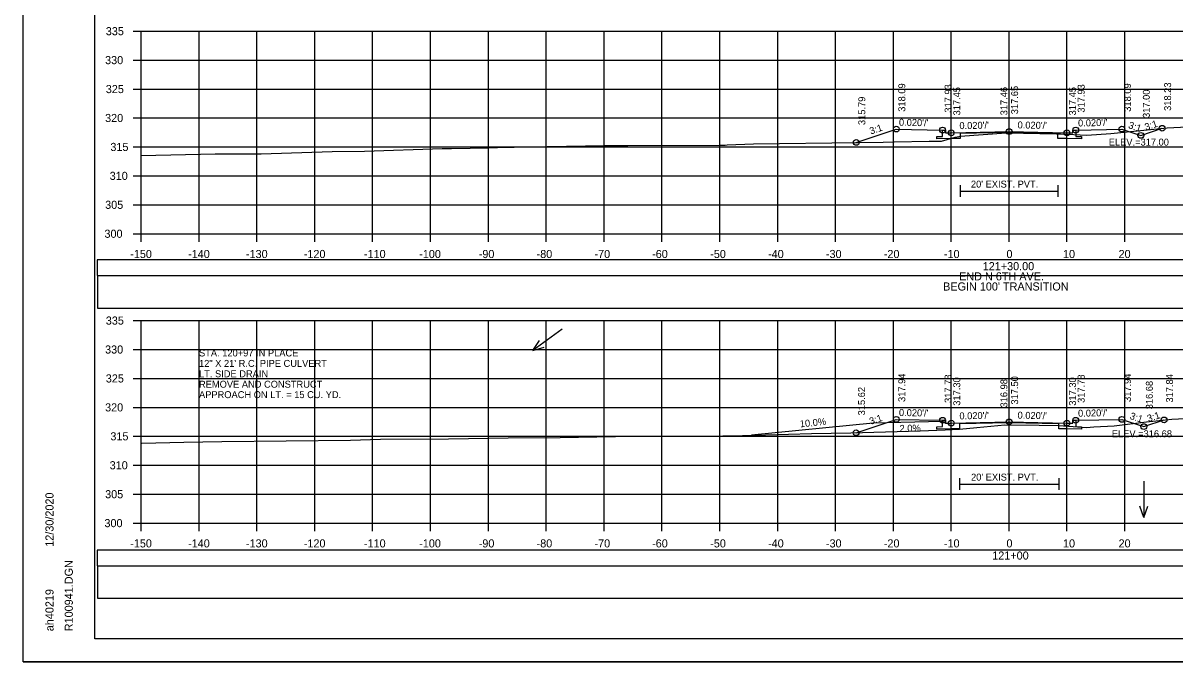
# Model space of a CAD drawing. Extents: x 1370538 to 1372872, y 376220 to 381127.
# Drawn here: x 1371871.6 to 1372070.6, y 380471.7 to 380582.1 of the extents above; entities that cross this region are included whole.
import ezdxf

# ---------------------------------------------------------------- set-up
doc = ezdxf.new("R2010")
doc.units = 0
for name, color, linetype in [('R_Border', 7, 'Continuous'), ('R_Border Notes', 7, 'Continuous'), ('R_Border PE', 7, 'Continuous'), ('R_Border Prem', 7, 'Continuous'), ('R_Dimension', 7, 'Continuous'), ('R_Fin Surface', 7, 'Continuous'), ('R_Grid', 7, 'Continuous'), ('R_No Plot', 7, 'Continuous'), ('R_Water', 7, 'Continuous'), ('R_Water Annot', 7, 'Continuous'), ('R_Xsect Elev', 7, 'Continuous'), ('R_Xsect Slope', 7, 'Continuous'), ('T_Detection Zones', 7, 'Continuous')]:
    doc.layers.add(name, color=color, linetype=linetype)

msp = doc.modelspace()

# ---------------------------------------------------------------- linework, layer by layer
at = {"layer": 'R_Border'}
for p, q in [((1372033.53, 380554.09), (1372033.53, 380552.09)), ((1372050.41, 380554.09), (1372050.41, 380552.09)), ((1372033.53, 380553.09), (1372050.41, 380553.09)), ((1372033.41, 380503.46), (1372033.41, 380501.46)), ((1372033.41, 380502.46), (1372050.55, 380502.46)), ((1372050.55, 380503.46), (1372050.55, 380501.46))]:
    msp.add_line(p, q, dxfattribs=at)
for points in [[(1372041.97, 380563.18), (1372033.53, 380563.01), (1372033.53, 380562.18), (1372031.97, 380562.15), (1372029.47, 380562.1), (1372029.47, 380562.52), (1372030.47, 380562.54), (1372030.47, 380563.63)], [(1372053.47, 380563.63), (1372053.47, 380562.54), (1372054.47, 380562.52), (1372054.47, 380562.1), (1372051.97, 380562.15), (1372050.41, 380562.18), (1372050.41, 380563.01), (1372041.97, 380563.18)], [(1372041.97, 380513.03), (1372033.41, 380512.86), (1372033.41, 380512.03), (1372031.97, 380512), (1372029.47, 380511.95), (1372029.47, 380512.37), (1372030.47, 380512.39), (1372030.47, 380513.48)], [(1372053.47, 380513.48), (1372053.47, 380512.39), (1372054.47, 380512.37), (1372054.47, 380511.95), (1372051.97, 380512), (1372050.55, 380512.03), (1372050.55, 380512.86), (1372041.97, 380513.03)]]:
    msp.add_lwpolyline(points, dxfattribs=at)
at = {"layer": 'R_Border Notes'}
for p, q in [((1371883.97, 380475.71), (1371883.97, 380681.17)), ((1371883.97, 380475.71), (1371883.97, 380475.71)), ((1372200.15, 380475.71), (1371883.97, 380475.71))]:
    msp.add_line(p, q, dxfattribs=at)
at = {"layer": 'R_Border Prem'}
for p, q in [((1371890.57, 380580.71), (1371891.97, 380580.71)), ((1371891.97, 380545.71), (1371891.97, 380580.71)), ((1371890.57, 380575.71), (1371891.97, 380575.71)), ((1371890.57, 380570.71), (1371891.97, 380570.71)), ((1371890.57, 380565.71), (1371891.97, 380565.71)), ((1371890.57, 380560.71), (1371891.97, 380560.71)), ((1371890.57, 380555.71), (1371891.97, 380555.71)), ((1371890.57, 380550.71), (1371891.97, 380550.71)), ((1371890.57, 380545.71), (1371891.97, 380545.71)), ((1371891.97, 380545.71), (1372191.97, 380545.71)), ((1371891.97, 380544.31), (1371891.97, 380545.71)), ((1371901.97, 380544.31), (1371901.97, 380545.71)), ((1371911.97, 380544.31), (1371911.97, 380545.71)), ((1371921.97, 380544.31), (1371921.97, 380545.71)), ((1371931.97, 380544.31), (1371931.97, 380545.71)), ((1371941.97, 380544.31), (1371941.97, 380545.71)), ((1371951.97, 380544.31), (1371951.97, 380545.71)), ((1371961.97, 380544.31), (1371961.97, 380545.71)), ((1371971.97, 380544.31), (1371971.97, 380545.71)), ((1371981.97, 380544.31), (1371981.97, 380545.71)), ((1371991.97, 380544.31), (1371991.97, 380545.71)), ((1372001.97, 380544.31), (1372001.97, 380545.71)), ((1372011.97, 380544.31), (1372011.97, 380545.71)), ((1372021.97, 380544.31), (1372021.97, 380545.71)), ((1372031.97, 380544.31), (1372031.97, 380545.71)), ((1372041.97, 380544.31), (1372041.97, 380545.71)), ((1372051.97, 380544.31), (1372051.97, 380545.71)), ((1372061.97, 380544.31), (1372061.97, 380545.71)), ((1371890.57, 380530.71), (1371891.97, 380530.71)), ((1371891.97, 380495.71), (1371891.97, 380530.71)), ((1371890.57, 380525.71), (1371891.97, 380525.71)), ((1371890.57, 380520.71), (1371891.97, 380520.71)), ((1371890.57, 380515.71), (1371891.97, 380515.71)), ((1371890.57, 380510.71), (1371891.97, 380510.71)), ((1371890.57, 380505.71), (1371891.97, 380505.71)), ((1371890.57, 380500.71), (1371891.97, 380500.71)), ((1371890.57, 380495.71), (1371891.97, 380495.71)), ((1371891.97, 380495.71), (1372191.97, 380495.71)), ((1371891.97, 380494.31), (1371891.97, 380495.71)), ((1371901.97, 380494.31), (1371901.97, 380495.71)), ((1371911.97, 380494.31), (1371911.97, 380495.71)), ((1371921.97, 380494.31), (1371921.97, 380495.71)), ((1371931.97, 380494.31), (1371931.97, 380495.71)), ((1371941.97, 380494.31), (1371941.97, 380495.71)), ((1371951.97, 380494.31), (1371951.97, 380495.71)), ((1371961.97, 380494.31), (1371961.97, 380495.71)), ((1371971.97, 380494.31), (1371971.97, 380495.71)), ((1371981.97, 380494.31), (1371981.97, 380495.71)), ((1371991.97, 380494.31), (1371991.97, 380495.71)), ((1372001.97, 380494.31), (1372001.97, 380495.71)), ((1372011.97, 380494.31), (1372011.97, 380495.71)), ((1372021.97, 380494.31), (1372021.97, 380495.71)), ((1372031.97, 380494.31), (1372031.97, 380495.71)), ((1372041.97, 380494.31), (1372041.97, 380495.71)), ((1372051.97, 380494.31), (1372051.97, 380495.71)), ((1372061.97, 380494.31), (1372061.97, 380495.71))]:
    msp.add_line(p, q, dxfattribs=at)
at = {"layer": 'R_Dimension'}
for points in [[(1371891.97, 380559.21), (1371904.78, 380559.49), (1371908.06, 380559.53), (1371912.7, 380559.5), (1371924.98, 380559.91), (1371930.55, 380559.97), (1371943.99, 380560.44), (1371945.59, 380560.45), (1371952.08, 380560.55), (1371953.55, 380560.59), (1371962.11, 380560.76), (1371972.09, 380560.96), (1371976.05, 380560.97), (1371991.87, 380561.03), (1371992.91, 380561.04), (1371993.23, 380561.06), (1371997.8, 380561.25), (1372015.83, 380561.5), (1372020.2, 380561.56), (1372022.08, 380561.57), (1372028.16, 380561.73), (1372029.8, 380561.7), (1372030.27, 380561.69), (1372031.24, 380561.98), (1372032.67, 380562.42), (1372033.3, 380562.54), (1372033.53, 380562.58), (1372041.46, 380563.17), (1372041.59, 380563.17), (1372050.15, 380563), (1372050.41, 380562.99), (1372050.85, 380562.98), (1372055.39, 380562.76), (1372059.54, 380563.05), (1372060.72, 380563.13), (1372062.95, 380563.4), (1372069.26, 380564.02), (1372086.66, 380564.89)], [(1371891.97, 380509.52), (1371892.1, 380509.52), (1371899.34, 380509.72), (1371905.92, 380509.79), (1371928.15, 380510.03), (1371933.31, 380510.21), (1371945.11, 380510.28), (1371955.42, 380510.45), (1371964.39, 380510.51), (1371977.09, 380510.76), (1371986.43, 380510.75), (1371989.02, 380510.76), (1371995.9, 380510.86), (1372007.82, 380511.2), (1372014.63, 380511.3), (1372026.59, 380511.64), (1372030.92, 380511.84), (1372033.41, 380511.97), (1372036.41, 380512.26), (1372041.21, 380512.7), (1372047.16, 380512.61), (1372050.55, 380512.55), (1372053.01, 380512.39), (1372055.36, 380512.25), (1372056.59, 380512.34), (1372060.11, 380512.53), (1372065.7, 380513.19), (1372070.08, 380513.7), (1372082.49, 380514.33)]]:
    msp.add_lwpolyline(points, dxfattribs=at)
at = {"layer": 'R_Fin Surface'}
for points in [[(1372015.56, 380561.49), (1372022.47, 380563.79), (1372030.47, 380563.63), (1372030.97, 380563.63), (1372030.97, 380563.13), (1372031.97, 380563.15), (1372041.97, 380563.35)], [(1372041.97, 380563.35), (1372051.97, 380563.15), (1372052.97, 380563.13), (1372052.97, 380563.63), (1372053.47, 380563.63), (1372061.47, 380563.79), (1372064.73, 380562.71), (1372068.41, 380563.94)], [(1372015.52, 380511.33), (1372022.47, 380513.64), (1372030.47, 380513.48), (1372030.97, 380513.48), (1372030.97, 380512.98), (1372031.97, 380513), (1372041.97, 380513.2)], [(1372041.97, 380513.2), (1372051.97, 380513), (1372052.97, 380512.98), (1372052.97, 380513.48), (1372053.47, 380513.48), (1372061.47, 380513.64), (1372065.25, 380512.38), (1372068.74, 380513.54)]]:
    msp.add_lwpolyline(points, dxfattribs=at)
for points in [[(1371884.44, 380532.88), (1372199.45, 380532.88), (1372199.45, 380538.45), (1371884.44, 380538.45)], [(1371884.44, 380482.73), (1372199.45, 380482.73), (1372199.45, 380488.3), (1371884.44, 380488.3)]]:
    msp.add_lwpolyline(points, close=True, dxfattribs=at)
at = {"layer": 'R_Grid'}
for p, q in [((1371891.97, 380580.71), (1372191.97, 380580.71)), ((1371891.97, 380545.71), (1371891.97, 380580.71)), ((1371901.97, 380545.71), (1371901.97, 380580.71)), ((1371911.97, 380545.71), (1371911.97, 380580.71)), ((1371921.97, 380545.71), (1371921.97, 380580.71)), ((1371931.97, 380545.71), (1371931.97, 380580.71)), ((1371941.97, 380545.71), (1371941.97, 380580.71)), ((1371951.97, 380545.71), (1371951.97, 380580.71)), ((1371961.97, 380545.71), (1371961.97, 380580.71)), ((1371971.97, 380545.71), (1371971.97, 380580.71)), ((1371981.97, 380545.71), (1371981.97, 380580.71)), ((1371991.97, 380545.71), (1371991.97, 380580.71)), ((1372001.97, 380545.71), (1372001.97, 380580.71)), ((1372011.97, 380545.71), (1372011.97, 380580.71)), ((1372021.97, 380545.71), (1372021.97, 380580.71)), ((1372031.97, 380545.71), (1372031.97, 380580.71)), ((1372041.97, 380545.71), (1372041.97, 380580.71)), ((1372051.97, 380545.71), (1372051.97, 380580.71)), ((1372061.97, 380545.71), (1372061.97, 380580.71)), ((1371891.97, 380575.71), (1372191.97, 380575.71)), ((1371891.97, 380570.71), (1372191.97, 380570.71)), ((1371891.97, 380565.71), (1372191.97, 380565.71)), ((1371891.97, 380560.71), (1372191.97, 380560.71)), ((1371891.97, 380555.71), (1372191.97, 380555.71)), ((1371891.97, 380550.71), (1372191.97, 380550.71)), ((1371891.97, 380545.71), (1372191.97, 380545.71)), ((1371891.97, 380530.71), (1372191.97, 380530.71)), ((1371891.97, 380495.71), (1371891.97, 380530.71)), ((1371901.97, 380495.71), (1371901.97, 380530.71)), ((1371911.97, 380495.71), (1371911.97, 380530.71)), ((1371921.97, 380495.71), (1371921.97, 380530.71)), ((1371931.97, 380495.71), (1371931.97, 380530.71)), ((1371941.97, 380495.71), (1371941.97, 380530.71)), ((1371951.97, 380495.71), (1371951.97, 380530.71)), ((1371961.97, 380495.71), (1371961.97, 380530.71)), ((1371971.97, 380495.71), (1371971.97, 380530.71)), ((1371981.97, 380495.71), (1371981.97, 380530.71)), ((1371991.97, 380495.71), (1371991.97, 380530.71)), ((1372001.97, 380495.71), (1372001.97, 380530.71)), ((1372011.97, 380495.71), (1372011.97, 380530.71)), ((1372021.97, 380495.71), (1372021.97, 380530.71)), ((1372031.97, 380495.71), (1372031.97, 380530.71)), ((1372041.97, 380495.71), (1372041.97, 380530.71)), ((1372051.97, 380495.71), (1372051.97, 380530.71)), ((1372061.97, 380495.71), (1372061.97, 380530.71)), ((1371891.97, 380525.71), (1372191.97, 380525.71)), ((1371891.97, 380520.71), (1372191.97, 380520.71)), ((1371891.97, 380515.71), (1372191.97, 380515.71)), ((1371891.97, 380510.71), (1372191.97, 380510.71)), ((1371891.97, 380505.71), (1372191.97, 380505.71)), ((1371891.97, 380500.71), (1372191.97, 380500.71)), ((1371891.97, 380495.71), (1372191.97, 380495.71))]:
    msp.add_line(p, q, dxfattribs=at)
at = {"layer": 'R_No Plot'}
msp.add_line((1371871.57, 380471.73), (1372204.9, 380471.73), dxfattribs=at)
for points in [[(1371871.56, 380685.06), (1372204.9, 380685.06), (1372204.9, 380471.72), (1371871.56, 380471.72)], [(1372117.89, 380681.17), (1372117.89, 380671.29), (1372153.62, 380671.29), (1372153.62, 380668.37), (1372176.82, 380668.37), (1372176.82, 380644.03), (1372200.15, 380644.03), (1372200.15, 380475.71), (1371883.97, 380475.71), (1371883.97, 380681.17)]]:
    msp.add_lwpolyline(points, close=True, dxfattribs=at)
for centre in [(1372022.47, 380563.79), (1372030.47, 380563.63), (1372031.97, 380563.15), (1372041.97, 380563.35), (1372041.97, 380563.35), (1372051.97, 380563.15), (1372053.47, 380563.63), (1372061.47, 380563.79), (1372068.41, 380563.94), (1372015.56, 380561.49), (1372064.73, 380562.71), (1372022.47, 380513.64), (1372030.47, 380513.48), (1372041.97, 380513.2), (1372041.97, 380513.2), (1372053.47, 380513.48), (1372061.47, 380513.64), (1372068.74, 380513.54), (1372015.52, 380511.33), (1372031.97, 380513), (1372051.97, 380513), (1372065.25, 380512.38)]:
    msp.add_circle(centre, 0.5, dxfattribs=at)
at = {"layer": 'R_Water'}
for p, q in [((1372018.47, 380513.01), (1371997.45, 380510.9)), ((1372030.47, 380513.25), (1372018.47, 380513.01)), ((1372030.97, 380513), (1372030.47, 380513.25))]:
    msp.add_line(p, q, dxfattribs=at)
at = {"layer": 'R_Water Annot'}
for p, q in [((1371964.74, 380529.23), (1371959.64, 380525.56)), ((1371959.64, 380525.56), (1371960.79, 380527.25)), ((1371959.64, 380525.56), (1371961.61, 380526.12)), ((1372065.25, 380502.98), (1372065.25, 380496.69)), ((1372065.25, 380496.69), (1372064.55, 380498.62)), ((1372065.25, 380496.69), (1372065.95, 380498.62))]:
    msp.add_line(p, q, dxfattribs=at)
at = {"layer": 'R_Xsect Elev'}
for p, q in [((1372041.97, 380563.17), (1372041.97, 380573.17)), ((1372041.97, 380512.69), (1372041.97, 380522.69))]:
    msp.add_line(p, q, dxfattribs=at)
at = {"layer": 'T_Detection Zones'}
for points in [[(1371884.38, 380538.51), (1372199.5, 380538.51), (1372199.5, 380541.21), (1371884.38, 380541.21)], [(1371884.38, 380488.35), (1372199.5, 380488.35), (1372199.5, 380491.06), (1371884.38, 380491.06)]]:
    msp.add_lwpolyline(points, close=True, dxfattribs=at)

# ---------------------------------------------------------------- texts
at = {"layer": 'R_Border Notes'}
for s, p in [('12/30/2020', (1371876.83, 380491.63)), ('R100941.DGN', (1371880.16, 380477.03)), ('ah40219', (1371876.83, 380477.03))]:
    msp.add_text(s, height=1.4, rotation=90, dxfattribs=at).set_placement(p)
at = {"layer": 'R_Border PE'}
for s, p in [('335', (1371885.86, 380580.01)), ('330', (1371885.74, 380575.01)), ('325', (1371885.86, 380570.01)), ('320', (1371885.74, 380565.01)), ('315', (1371886.65, 380560.01)), ('310', (1371886.53, 380555.01)), ('305', (1371885.75, 380550.01)), ('300', (1371885.63, 380545.01)), ('-150', (1371890.08, 380541.51)), ('-140', (1371900.08, 380541.51)), ('-130', (1371910.08, 380541.51)), ('-120', (1371920.08, 380541.51)), ('-110', (1371930.47, 380541.51)), ('-100', (1371940.02, 380541.51)), ('-90', (1371950.31, 380541.51)), ('-80', (1371960.31, 380541.51)), ('-70', (1371970.31, 380541.51)), ('-60', (1371980.27, 380541.51)), ('-50', (1371990.31, 380541.51)), ('-40', (1372000.31, 380541.51)), ('-30', (1372010.31, 380541.51)), ('-20', (1372020.31, 380541.51)), ('-10', (1372030.7, 380541.51)), ('0', (1372041.51, 380541.51)), ('10', (1372051.28, 380541.51)), ('20', (1372060.88, 380541.51)), ('121+30.00', (1372037.4, 380539.41)), ('END N 6TH AVE.', (1372033.32, 380537.65)), ("BEGIN 100' TRANSITION", (1372030.56, 380535.9)), ('335', (1371885.86, 380530.01)), ('330', (1371885.74, 380525.01)), ('325', (1371885.86, 380520.01)), ('320', (1371885.74, 380515.01)), ('315', (1371886.65, 380510.01)), ('310', (1371886.53, 380505.01)), ('305', (1371885.75, 380500.01)), ('300', (1371885.63, 380495.01)), ('-150', (1371890.08, 380491.51)), ('-140', (1371900.08, 380491.51)), ('-130', (1371910.08, 380491.51)), ('-120', (1371920.08, 380491.51)), ('-110', (1371930.47, 380491.51)), ('-100', (1371940.02, 380491.51)), ('-90', (1371950.31, 380491.51)), ('-80', (1371960.31, 380491.51)), ('-70', (1371970.31, 380491.51)), ('-60', (1371980.27, 380491.51)), ('-50', (1371990.31, 380491.51)), ('-40', (1372000.31, 380491.51)), ('-30', (1372010.31, 380491.51)), ('-20', (1372020.31, 380491.51)), ('-10', (1372030.7, 380491.51)), ('0', (1372041.51, 380491.51)), ('10', (1372051.28, 380491.51)), ('20', (1372060.88, 380491.51)), ('121+00', (1372039.05, 380489.41))]:
    msp.add_text(s, height=1.4, dxfattribs=at).set_placement(p)
at = {"layer": 'R_Water'}
for p in [(1372035.37, 380553.69), (1372035.39, 380503.06)]:
    msp.add_text("20' EXIST. PVT.", height=1.2, dxfattribs=at).set_placement(p)
at = {"layer": 'R_Water Annot'}
for s, p in [('STA. 120+97 IN PLACE', (1371901.97, 380524.51)), ('12" X 21\' R.C. PIPE CULVERT', (1371901.97, 380522.71)), ('LT. SIDE DRAIN', (1371901.97, 380520.91)), ('REMOVE AND CONSTRUCT', (1371901.97, 380519.11)), ('APPROACH ON LT. = 15 CU. YD.', (1371901.97, 380517.31))]:
    msp.add_text(s, height=1.2, dxfattribs=at).set_placement(p)
at = {"layer": 'R_Xsect Elev'}
for s, rotation, p in [('318.09', 90, (1372024.02, 380566.79)), ('317.93', 90, (1372032.02, 380566.63)), ('317.93', 90, (1372055.02, 380566.63)), ('318.09', 90, (1372063.02, 380566.79)), ('318.23', 90, (1372069.96, 380566.94)), ('317.45', 90, (1372033.52, 380566.15)), ('317.46', 90, (1372041.67, 380566.17)), ('317.65', 90, (1372043.52, 380566.35)), ('317.45', 90, (1372053.52, 380566.15)), ('317.00', 90, (1372066.28, 380565.71)), ('315.79', 90, (1372017.11, 380564.49)), ('317.94', 90, (1372024.02, 380516.64)), ('317.78', 90, (1372032.02, 380516.48)), ('317.30', 90, (1372033.52, 380516)), ('316.98', 90, (1372041.67, 380515.69)), ('317.50', 90, (1372043.52, 380516.2)), ('317.30', 90, (1372053.52, 380516)), ('317.78', 90, (1372055.02, 380516.48)), ('317.94', 90, (1372063.02, 380516.64)), ('316.68', 90, (1372066.8, 380515.38)), ('317.84', 90, (1372070.29, 380516.54)), ('315.62', 90, (1372017.07, 380514.33)), ('10.0%', 5.7106, (1372005.86, 380512.25)), ('2.0%', 1.1458, (1372023.04, 380511.47))]:
    msp.add_text(s, height=1.2, rotation=rotation, dxfattribs=at).set_placement(p)
for s, p in [('ELEV.=317.00', (1372059.19, 380560.94)), ('ELEV.=316.68', (1372059.72, 380510.55))]:
    msp.add_text(s, height=1.2, dxfattribs=at).set_placement(p)
at = {"layer": 'R_Xsect Slope'}
for s, rotation, p in [("0.020'/'", 358.8542, (1372022.92, 380564.38)), ("0.020'/'", 1.1458, (1372053.89, 380564.24)), ('3:1', 18.4349, (1372018.07, 380562.85)), ("0.020'/'", 1.1458, (1372033.39, 380563.78)), ("0.020'/'", 358.8542, (1372043.42, 380563.92)), ('3:1', 341.5651, (1372062.47, 380563.99)), ('3:1', 18.4349, (1372065.62, 380563.53)), ('3:1', 18.4349, (1372018.04, 380512.7)), ("0.020'/'", 358.8542, (1372022.92, 380514.23)), ("0.020'/'", 1.1458, (1372033.39, 380513.63)), ("0.020'/'", 358.8542, (1372043.42, 380513.77)), ("0.020'/'", 1.1458, (1372053.89, 380514.09)), ('3:1', 341.5651, (1372062.73, 380513.75)), ('3:1', 18.4349, (1372066.05, 380513.17))]:
    msp.add_text(s, height=1.2, rotation=rotation, dxfattribs=at).set_placement(p)

doc.saveas('drawing.dxf')
